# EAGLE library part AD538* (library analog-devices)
Real-Time Analog Computational Unit (ACU)
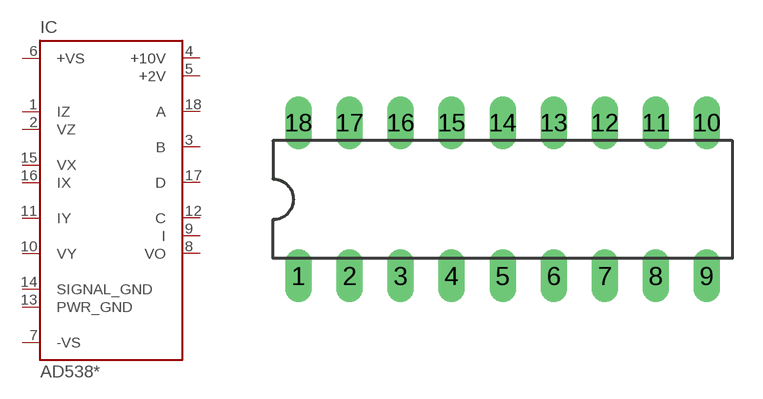
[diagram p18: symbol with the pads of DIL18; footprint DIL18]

Designator prefix IC

## AD538AD (MF: ALTERA CORPORATION; MPN: AD538AD; OC_FARNELL: 402667; OC_NEWARK: 05F6949), AD538BD (MF: ALTERA CORPORATION; MPN: AD538BD; OC_FARNELL: 1530988; OC_NEWARK: 05F6950), AD538SD (MF: ALTERA CORPORATION; MPN: AD538SD; OC_FARNELL: unknown; OC_NEWARK: 16F3434)  [DIL18]
1  IZ  pas
2  VZ  in
3  B  out
4  +10V  out
5  +2V  out
6  +VS  pwr
7  -VS  pwr
8  VO  out
9  I  pas
10  VY  in
11  IY  pas
12  C  pas
13  PWR_GND  pwr
14  SIGNAL_GND  pwr
15  VX  in
16  IX  pas
17  D  pas
18  A  pas

## Footprint DIL18 (pad centres in mm)
Dual In Line Package
drill 0.813 long: 1 -10.16,-3.81; 2 -7.62,-3.81; 3 -5.08,-3.81; 4 -2.54,-3.81; 5 0,-3.81; 6 2.54,-3.81; 7 5.08,-3.81; 8 7.62,-3.81; 9 10.16,-3.81; 10 10.16,3.81; 11 7.62,3.81; 12 5.08,3.81; 13 2.54,3.81; 14 0,3.81; 15 -2.54,3.81; 16 -5.08,3.81; 17 -7.62,3.81; 18 -10.16,3.81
